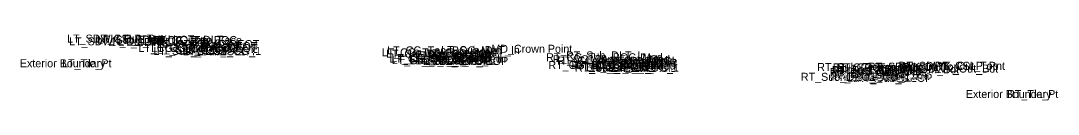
# Model space of a CAD drawing. Extents: x -26 to 6300, y -10 to 9528.
# Drawn here: x 1080.8 to 1210.4, y 8010.5 to 8018.8 of the extents above; entities that cross this region are included whole.
import ezdxf

# ---------------------------------------------------------------- set-up
doc = ezdxf.new("R2010")
doc.units = 0
doc.layers.add('Default', color=7, linetype='Continuous')

msp = doc.modelspace()

# ---------------------------------------------------------------- texts
at = {"layer": 'Default'}
for s, p in [('LT_SDWK_Out_Top', (1086.58, 8017.75)), ('LT_SDWK_Out_Bot', (1086.83, 8017.41)), ('LT_CSLP_Pnt', (1090.1, 8017.75)), ('LT_Sub_Trench_Out_DLT', (1090.32, 8017.6)), ('LT_SDWK_In_Top', (1092.74, 8017.65)), ('LT_CG_Top_BOC', (1096.81, 8017.56)), ('LT_CG_Top_Face', (1097.34, 8017.56)), ('LT_SDWK_In_Bot', (1092.99, 8017.31)), ('LT_CG1_Shelf_Out', (1095.48, 8016.59)), ('LT_CG_Bot_BOC', (1097.09, 8016.57)), ('LT_Sub_OEOT_CG_1', (1097.36, 8016.22)), ('LT_Sub_OEOP', (1097.79, 8016.35)), ('LT_CG_Top_Gut', (1097.87, 8017.06)), ('LT_PV2_OEOT', (1100.99, 8016.81)), ('LT_PV3_OEOT', (1100.99, 8016.56)), ('LT_Sub_OEOT', (1101.04, 8016.18)), ('LT_PV1_OEOT', (1101.23, 8017.06)), ('LT_CG_Bot_IE', (1101.34, 8016.47)), ('LT_CG_Top_BOC_Med', (1126.57, 8016.28)), ('LT_Sub_DLT_In', (1133.32, 8016.32)), ('MD_Crown Point', (1139.58, 8016.48)), ('LT_CG_Top_Face_Med', (1125.87, 8016.03)), ('LT_CG_Top_Gut_Med', (1126.42, 8015.87)), ('LT_CG_Bot_BOC_Med', (1126.85, 8015.25)), ('LT_CG_Bot_IE_Med', (1127.09, 8015.31)), ('LT_Sub_IEOT_CG_1', (1127.13, 8015.06)), ('LT_PV2_OEEOP', (1129.29, 8015.65)), ('LT_PV3_OEEOP', (1129.29, 8015.4)), ('LT_Sub_OEEOP', (1129.33, 8015.02)), ('LT_PV2_IEEOP', (1130.05, 8015.65)), ('LT_Sub_IEEOP', (1130.09, 8015.02)), ('LT_CG1_Shelf_In', (1130.71, 8015.23)), ('LT_PV2_PGL', (1131.26, 8015.65)), ('LT_Sub_PGL', (1131.31, 8015.02)), ('LT_PV1_PGL', (1131.5, 8015.9)), ('LT_Sub_IEOP', (1133.06, 8014.97)), ('RT_CG_Top_BOC_Med', (1146.43, 8015.42)), ('RT_CG_Top_Face_Med', (1147.25, 8015.17)), ('RT_CG_Top_Gut_Med', (1147.8, 8015.01)), ('RT_Sub_DLT_In', (1148.91, 8015.65)), ('RT_PV1_PGL', (1154.38, 8014.98)), ('Exterior Boundary', (1080.67, 8014.67)), ('LT_Tie_Pt', (1085.95, 8014.67)), ('RT_CG_Bot_BOC_Med', (1146.71, 8014.45)), ('RT_CG1_Shelf_In', (1149.57, 8014.47)), ('RT_CG_Bot_IE_Med', (1149.98, 8014.39)), ('RT_Sub_IEOT_CG_1', (1150.01, 8014.14)), ('RT_Sub_IEOP', (1151.42, 8014.23)), ('RT_PV2_OEEOP', (1152.17, 8014.73)), ('RT_PV3_OEEOP', (1152.17, 8014.48)), ('RT_Sub_OEEOP', (1152.21, 8014.1)), ('RT_PV2_IEEOP', (1152.93, 8014.73)), ('RT_Sub_IEEOP', (1152.97, 8014.1)), ('RT_PV2_PGL', (1154.15, 8014.73)), ('RT_Sub_PGL', (1154.19, 8014.1)), ('RT_Sub_Trench_Out_DLT', (1180.29, 8014.2)), ('RT_PV2_OEOT', (1181.87, 8013.57)), ('RT_PV1_OEOT', (1182.11, 8013.82)), ('RT_CG_Top_Face', (1182.22, 8014.16)), ('RT_CG_Top_BOC', (1182.69, 8014.16)), ('RT_CG_Top_Gut', (1182.75, 8013.66)), ('RT_SDWK_In_Top', (1186.62, 8014.25)), ('RT_SDWK_In_Bot', (1186.87, 8013.91)), ('RT_SDWK_Out_Top', (1190.46, 8014.35)), ('RT_SDWK_Out_Bot', (1190.71, 8014.01)), ('RT_CSLP_Pnt', (1194.98, 8014.35)), ('RT_Sub_OEOT_CG_1', (1178.25, 8012.98)), ('RT_PV3_OEOT', (1181.87, 8013.32)), ('RT_Sub_OEOT', (1181.92, 8012.94)), ('RT_CG_Bot_IE', (1182.22, 8013.23)), ('RT_CG1_Shelf_Out', (1182.36, 8013.11)), ('RT_CG_Bot_BOC', (1182.97, 8013.13)), ('RT_Sub_OEOP', (1185.17, 8012.85)), ('Exterior Boundary', (1198.86, 8010.83)), ('RT_Tie_Pt', (1204.02, 8010.83))]:
    msp.add_text(s, height=1, dxfattribs=at).set_placement(p)

doc.saveas('drawing.dxf')
